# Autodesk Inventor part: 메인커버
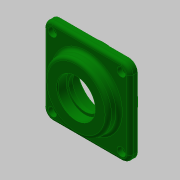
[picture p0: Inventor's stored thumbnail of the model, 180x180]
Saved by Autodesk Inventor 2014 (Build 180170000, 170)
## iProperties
Created: 2018-09
Part Number: 메인커버
Material: 알루미늄 6061
Document SubType Name: Modeling
Designer: mduedu
Density: 2.71 g/cm^3
Appearance: 진녹색
Mass: 178.463 g
Surface Area: 197.883 cm^2
Volume: 65.8536 cm^3
Author: mduedu
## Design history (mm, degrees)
sketch "스케치1"
  geometry: L1 (-40, -40)-(40, -40); L2 (40, -40)-(40, 40); L3 (40, 40)-(-40, 40); L4 (-40, 40)-(-40, -40); L5 (-40, -40)-(40, 40); L6 (40, -40)-(-40, 40); 1 further point
  constraints: 12 end point, 2 midpoint, 2 parallel, 1 horizontal, 1 perpendicular
  dimensions: "d0" = 80 distance of L3.end L2.end; "d1" = 80 distance of L2.end L1.end
extrude "돌출1" new body sketch "스케치1" distance "d2" = 7; taper "d3" = 0 deg
sketch "스케치2"
  geometry: C1 r 30 at (0, 0); 1 further point
  constraints: 1 centre point, 1 coincident
  dimensions: "d4" = 60 diameter of C1
extrude "돌출2" join sketch "스케치2" distance "d5" = 10; taper "d6" = 0 deg
sketch "스케치3"
  geometry: C1 r 32.5 at (0, 0); 1 further point
  constraints: 1 centre point, 1 coincident
  dimensions: "d7" = 65 diameter of C1
extrude "돌출3" join sketch "스케치3" distance "d8" = 9; taper "d9" = 0 deg
sketch "스케치4"
  geometry: L1 (-32.5, -9)-(32.5, -9) reference; L2 (30, 17)-(-30, 17) reference; L3 (0, 17)-(0, -9); L4 (0, -9)-(23.5, -9); L5 (23.5, -9)-(23.5, 5); L6 (23.5, 5)-(0, 5); L7 (0, 5)-(0, -9); L8 (0, 5)-(15, 5); L9 (15, 5)-(15, 8.7); L10 (15, 8.7)-(0, 8.7); L11 (0, 8.7)-(0, 5); L12 (0, 8.7)-(17.5, 8.7); L13 (17.5, 8.7)-(17.5, 17); L14 (17.5, 17)-(0, 17); L15 (0, 17)-(0, 8.7); 1 further point
  constraints: 26 end point, 6 parallel, 3 horizontal, 3 perpendicular, 2 midpoint, 1 point on line
  dimensions: "d10" = 14 distance of L4.end L5.end; "d12" = 8.3 distance of L12.end L13.end; "d13" = 35 diameter of L13 L3; "d14" = 30 diameter of L9 L3; "d15" = 47 diameter of L5 L3
revolve "회전1" sketch "스케치4" stored, may be unused: angle "d16" = 90 deg
fillet "모깎기1" dims "d17" = 8
fillet "모깎기2" dims "d18" = 3
fillet "모깎기3" dims "d19" = 3
chamfer "모따기1" distance "d20" = 0.8; stored, may be unused: second distance "d21" = 2, angle "d22" = 30 deg
chamfer "모따기2" distance "d23" = 1; stored, may be unused: second distance "d24" = 2, angle "d25" = 30 deg
fillet "모깎기4" dims "d26" = 0.3
sketch "스케치5"
  geometry: A1 r 8 centre (-32, 32) between (-32, 40) and (-40, 32) reference; A2 r 8 centre (-32, -32) between (-40, -32) and (-32, -40) reference; A3 r 8 centre (32, -32) between (32, -40) and (40, -32) reference; A4 r 8 centre (32, 32) between (40, 32) and (32, 40) reference; 5 further points
  constraints: 4 coincident
hole "구멍1" sketch "스케치5" at (-32, 32), (32, 32), (32, -32), (-32, -32) diameter "d27" = 4.5; stored, may be unused: countersink angle "d31" = 90 deg, drill point angle "d33" = 118 deg; dims "d28" = 6, "d29" = 8, "d30" = 4.4, "d32" = 8
node "솔리드1"
